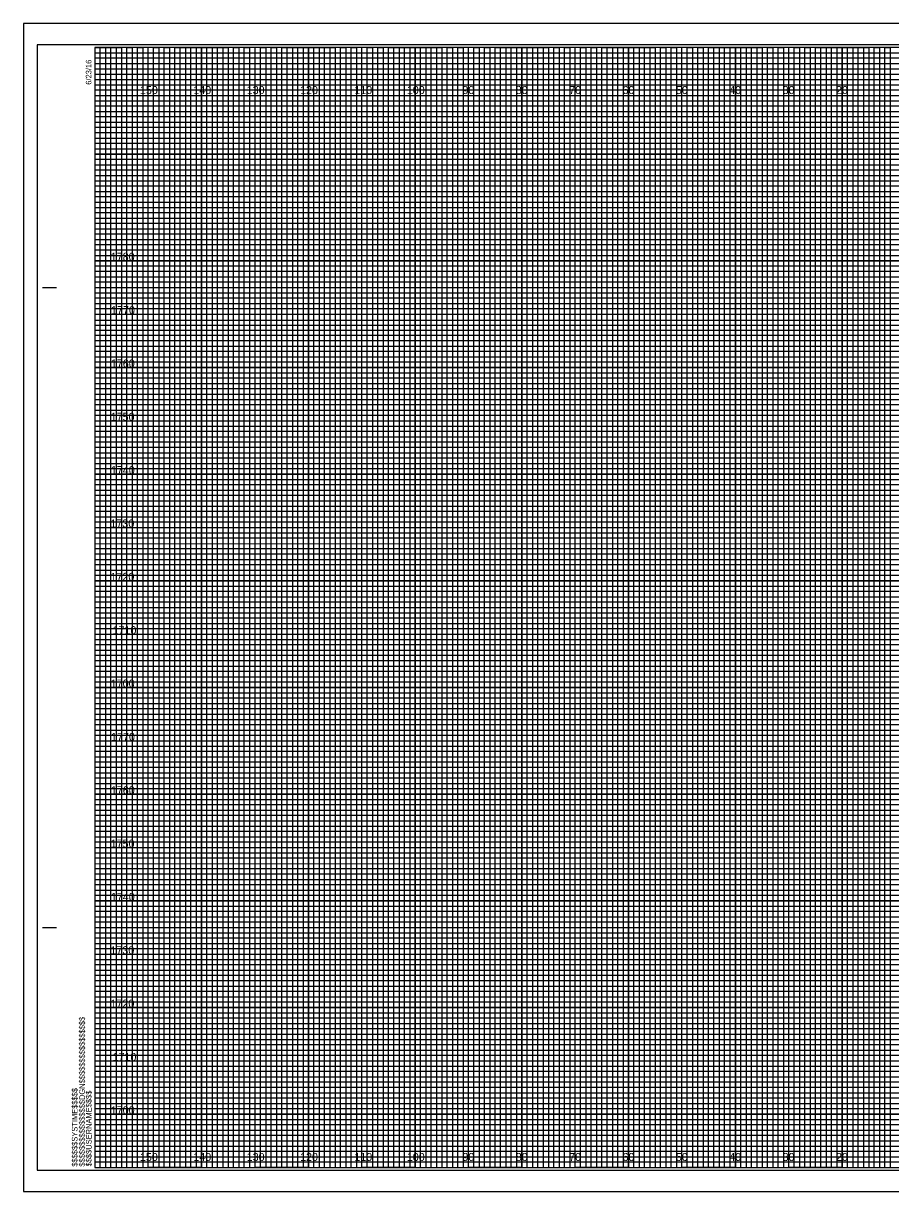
# Model space of a CAD drawing. Extents: x -419 to 4739, y -630 to 13534.
# Drawn here: x 4400.7 to 4563.2, y 665 to 884 of the extents above; entities that cross this region are included whole.
import ezdxf

# ---------------------------------------------------------------- set-up
doc = ezdxf.new("R2010")
doc.units = 0
for name, color, linetype in [('Old_Level_62', 7, 'Continuous'), ('Pattern 1', 7, 'Continuous'), ('Pattern 18', 7, 'Continuous'), ('Pattern 4', 7, 'Continuous'), ('Pattern 5', 7, 'Continuous'), ('Prop Dimension', 7, 'Continuous'), ('Prop Horizontal Alignment', 7, 'Continuous'), ('Raster_Level_0', 7, 'Continuous'), ('Scratch_Level_0', 7, 'Continuous'), ('Scratch_Level_3', 7, 'Continuous'), ('Scratch_Level_5', 7, 'Continuous')]:
    doc.layers.add(name, color=color, linetype=linetype)

msp = doc.modelspace()

# ---------------------------------------------------------------- linework, layer by layer
at = {"layer": 'Old_Level_62'}
for p, q in [((4404.33, 834.53), (4406.83, 834.53)), ((4404.43, 834.53), (4406.93, 834.53)), ((4404.33, 714.53), (4406.83, 714.53)), ((4404.43, 714.53), (4406.93, 714.53)), ((4414.13, 669.53), (4414.13, 669.53)), ((4414.13, 669.53), (4414.13, 669.53)), ((4414.13, 669.53), (4414.13, 669.53)), ((4414.13, 669.53), (4414.13, 669.53)), ((4414.13, 669.53), (4414.13, 669.53)), ((4414.13, 669.53), (4414.13, 669.53)), ((4414.13, 669.53), (4414.13, 669.53))]:
    msp.add_line(p, q, dxfattribs=at)
msp.add_lwpolyline([(4734.13, 879.53), (4414.13, 879.53), (4414.13, 669.53), (4734.13, 669.53)], close=True, dxfattribs=at)
at = {"layer": 'Pattern 18'}
msp.add_lwpolyline([(4400.73, 665.03), (4737.43, 665.03), (4737.43, 884.03), (4400.73, 884.03)], close=True, dxfattribs=at)
at = {"layer": 'Pattern 4'}
for p, q in [((4414.13, 878.53), (4674.13, 878.53)), ((4674.13, 877.51), (4414.13, 877.51)), ((4414.13, 877.51), (4414.13, 876.53)), ((4414.13, 876.53), (4674.13, 876.53)), ((4674.13, 875.42), (4414.13, 875.42)), ((4414.13, 875.42), (4414.13, 873.53)), ((4414.13, 873.53), (4734.13, 873.53))]:
    msp.add_line(p, q, dxfattribs=at)
for points in [[(4414.13, 872.53), (4684.13, 872.53), (4734.13, 872.53), (4734.13, 871.53), (4414.13, 871.53)], [(4414.13, 870.53), (4734.13, 870.53), (4734.13, 868.53), (4414.13, 868.53)], [(4414.13, 867.53), (4734.13, 867.53), (4734.13, 866.53), (4414.13, 866.51)], [(4414.13, 865.53), (4734.13, 865.53), (4734.13, 863.53), (4414.13, 863.53)], [(4414.13, 862.53), (4734.13, 862.53), (4734.13, 861.53), (4414.13, 861.53)], [(4414.13, 860.53), (4734.13, 860.53), (4734.13, 858.53), (4414.13, 858.53)], [(4414.13, 857.53), (4734.13, 857.53), (4734.13, 856.53), (4414.13, 856.53)], [(4414.13, 855.53), (4734.13, 855.53), (4734.13, 853.53), (4414.13, 853.53)], [(4414.13, 852.53), (4734.13, 852.53), (4734.13, 851.53), (4414.13, 851.53)], [(4414.13, 850.53), (4734.13, 850.53), (4734.13, 848.53), (4414.13, 848.53)], [(4414.13, 847.53), (4734.13, 847.53), (4734.13, 846.53), (4414.13, 846.53)], [(4414.13, 845.53), (4734.13, 845.53), (4734.13, 843.48), (4734.13, 842.53), (4734.13, 841.53), (4414.13, 841.53)], [(4414.13, 843.53), (4734.13, 843.53), (4734.13, 842.53), (4414.13, 842.53)], [(4414.13, 840.53), (4734.13, 840.53), (4734.13, 838.53), (4414.13, 838.56)], [(4414.13, 838.56), (4734.13, 838.53), (4734.13, 837.53), (4414.13, 837.53)], [(4414.13, 836.53), (4734.13, 836.53), (4734.13, 835.53), (4414.13, 835.53)], [(4414.13, 833.53), (4734.13, 833.53), (4734.13, 832.53), (4414.13, 832.53)], [(4414.13, 831.53), (4734.13, 831.53), (4734.13, 830.53), (4414.13, 830.53)], [(4414.06, 828.42), (4734.13, 828.42), (4734.13, 827.41), (4414.06, 827.41)], [(4414.13, 826.53), (4734.13, 826.53), (4734.13, 825.53), (4414.13, 825.53)], [(4414.13, 823.53), (4734.13, 823.53), (4734.13, 822.53), (4414.13, 822.53)], [(4414.13, 821.53), (4734.13, 821.53), (4734.13, 820.53), (4414.13, 820.53)], [(4414.13, 818.53), (4734.13, 818.53), (4734.13, 817.53), (4414.13, 817.53)], [(4414.13, 816.53), (4734.13, 816.53), (4734.13, 815.53), (4414.13, 815.53)], [(4414.13, 813.53), (4734.13, 813.53), (4734.13, 812.53), (4414.13, 812.53)], [(4414.13, 811.53), (4734.13, 811.53), (4734.13, 810.53), (4414.13, 810.53)], [(4414.13, 808.53), (4734.13, 808.53), (4734.12, 807.51), (4414.13, 807.53)], [(4414.13, 806.53), (4734.13, 806.53), (4734.13, 805.53), (4414.13, 805.53)], [(4414.13, 803.53), (4734.13, 803.53), (4734.13, 802.53), (4414.13, 802.53)], [(4414.13, 801.53), (4734.13, 801.53), (4734.13, 800.53), (4414.13, 800.53)], [(4414.13, 798.53), (4734.13, 798.53), (4734.13, 797.53), (4414.13, 797.53)], [(4414.13, 796.53), (4734.13, 796.53), (4734.13, 795.53), (4414.13, 795.53)], [(4414.13, 793.53), (4734.13, 793.53), (4734.13, 792.53), (4414.13, 792.53)], [(4414.13, 791.53), (4734.13, 791.53), (4734.13, 790.53), (4414.13, 790.53)], [(4414.13, 788.53), (4734.13, 788.53), (4734.13, 787.53), (4414.13, 787.53)], [(4414.13, 786.52), (4734.2, 786.44), (4734.13, 785.53), (4414.13, 785.53)], [(4414.13, 783.53), (4734.13, 783.53), (4734.13, 782.53), (4414.13, 782.53)], [(4414.13, 781.53), (4734.13, 781.53), (4734.13, 780.53), (4414.13, 780.53)], [(4414.13, 778.53), (4734.13, 778.53), (4734.13, 777.53), (4414.13, 777.53)], [(4414.13, 776.53), (4734.13, 776.53), (4734.13, 775.53), (4414.13, 775.53)], [(4414.13, 773.53), (4734.13, 773.53), (4734.13, 772.53), (4414.13, 772.53)], [(4414.13, 771.53), (4734.13, 771.53), (4734.13, 770.53), (4414.13, 770.53)], [(4414.13, 768.53), (4734.13, 768.53), (4734.13, 767.53), (4414.13, 767.53)], [(4414.13, 766.53), (4734.13, 766.53), (4734.13, 765.53), (4414.13, 765.53)], [(4414.13, 763.53), (4734.13, 763.53), (4734.13, 762.53), (4414.13, 762.53)], [(4414.13, 761.53), (4734.13, 761.53), (4734.13, 760.53), (4414.13, 760.53)], [(4414.13, 758.53), (4734.13, 758.53), (4734.13, 757.53), (4414.13, 757.53)], [(4414.13, 756.53), (4734.13, 756.53), (4734.13, 755.53), (4414.13, 755.53)], [(4414.13, 753.53), (4734.13, 753.53), (4734.13, 752.53), (4414.13, 752.53)], [(4414.13, 751.53), (4734.13, 751.53), (4734.13, 750.53), (4414.13, 750.53)], [(4414.13, 748.53), (4734.13, 748.53), (4734.12, 747.51), (4414.13, 747.53)], [(4414.13, 746.53), (4734.13, 746.53), (4734.13, 745.53), (4414.13, 745.53)], [(4414.13, 743.53), (4734.13, 743.53), (4734.13, 742.53), (4414.13, 742.53)], [(4414.13, 741.53), (4734.13, 741.53), (4734.13, 740.53), (4414.13, 740.53)], [(4414.13, 738.53), (4734.13, 738.53), (4734.13, 737.53), (4414.13, 737.53)], [(4414.13, 736.53), (4734.13, 736.53), (4734.13, 735.53), (4414.13, 735.53)], [(4414.13, 733.53), (4734.13, 733.53), (4734.13, 732.53), (4414.13, 732.53)], [(4414.13, 731.53), (4734.13, 731.53), (4734.13, 730.53), (4414.13, 730.53)], [(4414.13, 728.53), (4734.13, 728.53), (4734.13, 727.53), (4414.13, 727.53)], [(4414.13, 726.52), (4734.2, 726.44), (4734.13, 725.53), (4414.13, 725.53)], [(4414.13, 723.53), (4734.13, 723.53), (4734.13, 722.53), (4414.13, 722.53)], [(4414.13, 721.53), (4734.13, 721.53), (4734.13, 720.53), (4414.13, 720.53)], [(4414.13, 718.53), (4734.13, 718.53), (4734.13, 717.53), (4414.13, 717.53)], [(4414.13, 716.53), (4734.13, 716.53), (4734.13, 715.53), (4414.13, 715.53)], [(4414.13, 713.53), (4734.13, 713.53), (4734.13, 712.53), (4414.13, 712.53)], [(4414.13, 711.53), (4734.13, 711.53), (4734.13, 710.53), (4414.13, 710.53)], [(4414.13, 708.53), (4734.13, 708.53), (4734.13, 707.53), (4414.13, 707.53)], [(4414.13, 706.53), (4734.13, 706.53), (4734.13, 705.53), (4414.13, 705.53)], [(4414.13, 703.53), (4734.13, 703.53), (4734.13, 702.53), (4414.13, 702.53)], [(4414.13, 701.53), (4734.13, 701.53), (4734.13, 700.53), (4414.13, 700.53)], [(4414.13, 698.53), (4734.13, 698.53), (4734.13, 697.53), (4414.13, 697.53)], [(4414.13, 696.53), (4734.13, 696.53), (4734.13, 695.53), (4414.13, 695.53)], [(4414.13, 693.53), (4734.13, 693.53), (4734.13, 692.53), (4414.13, 692.53)], [(4414.13, 691.53), (4734.13, 691.53), (4734.13, 690.53), (4414.13, 690.53)], [(4414.13, 688.53), (4734.13, 688.53), (4734.13, 687.53), (4414.13, 687.53)], [(4414.13, 686.53), (4734.13, 686.53), (4734.13, 685.53), (4414.13, 685.53)], [(4414.13, 683.53), (4734.13, 683.53), (4734.13, 682.53), (4414.13, 682.53)], [(4414.13, 681.53), (4734.13, 681.53), (4734.13, 680.53), (4414.13, 680.53)], [(4414.13, 678.53), (4734.13, 678.53), (4734.13, 677.53), (4414.13, 677.53)], [(4414.13, 676.53), (4734.13, 676.53), (4734.13, 675.53), (4414.13, 675.53)], [(4414.13, 673.53), (4734.13, 673.53), (4734.13, 672.53), (4414.13, 672.53)], [(4414.13, 671.53), (4734.13, 671.53), (4734.13, 670.53), (4414.13, 670.53)]]:
    msp.add_lwpolyline(points, dxfattribs=at)
at = {"layer": 'Pattern 5'}
for p, q in [((4737.43, 884.03), (4400.73, 884.03)), ((4400.73, 884.03), (4400.73, 665.03)), ((4400.73, 665.03), (4737.43, 665.03))]:
    msp.add_line(p, q, dxfattribs=at)
at = {"layer": 'Prop Dimension'}
for points in [[(4414.13, 669.53), (4415.13, 669.53), (4415.13, 879.53), (4416.13, 879.53), (4416.13, 669.53)], [(4416.13, 669.53), (4417.13, 669.53), (4417.13, 879.53), (4418.13, 879.53), (4418.13, 669.53)], [(4419.13, 669.53), (4420.13, 669.53), (4420.13, 879.53), (4421.13, 879.53), (4421.13, 669.53)], [(4421.13, 669.53), (4422.13, 669.53), (4422.13, 879.53), (4423.13, 879.53), (4423.13, 669.53)], [(4424.13, 669.53), (4425.13, 669.53), (4425.13, 879.53), (4426.13, 879.53), (4426.13, 669.53)], [(4426.13, 669.53), (4427.13, 669.53), (4427.13, 879.53), (4428.13, 879.53), (4428.13, 669.53)], [(4429.13, 669.53), (4430.13, 669.53), (4430.13, 879.53), (4431.13, 879.53), (4431.13, 669.53)], [(4431.13, 669.53), (4432.13, 669.53), (4432.13, 879.53), (4433.13, 879.53), (4433.13, 669.53)], [(4434.13, 669.53), (4435.13, 669.53), (4435.13, 879.53), (4436.13, 879.53), (4436.13, 669.53)], [(4436.13, 669.53), (4437.13, 669.53), (4437.13, 879.53), (4438.13, 879.53), (4438.13, 669.53)], [(4439.13, 669.53), (4440.13, 669.53), (4440.13, 879.53), (4441.13, 879.53), (4441.13, 669.53)], [(4441.13, 669.53), (4442.13, 669.53), (4442.13, 879.53), (4443.13, 879.53), (4443.13, 669.53)], [(4444.13, 669.53), (4445.13, 669.53), (4445.13, 879.53), (4446.13, 879.53), (4446.13, 669.53)], [(4446.13, 669.53), (4447.13, 669.53), (4447.13, 879.53), (4448.13, 879.53), (4448.13, 669.53)], [(4449.13, 669.53), (4450.13, 669.53), (4450.13, 879.53), (4451.13, 879.53), (4451.13, 669.53)], [(4451.13, 669.53), (4452.13, 669.53), (4452.13, 879.53), (4453.13, 879.53), (4453.13, 669.53)], [(4454.13, 669.53), (4455.13, 669.53), (4455.13, 879.53), (4456.13, 879.53), (4456.13, 669.53)], [(4456.13, 669.53), (4457.13, 669.53), (4457.13, 879.53), (4458.13, 879.53), (4458.13, 669.53)], [(4459.13, 669.53), (4460.13, 669.53), (4460.13, 879.53), (4461.13, 879.53), (4461.13, 669.53)], [(4461.13, 669.53), (4462.13, 669.53), (4462.13, 879.53), (4463.13, 879.53), (4463.13, 669.53)], [(4464.13, 669.53), (4465.13, 669.53), (4465.13, 879.53), (4466.13, 879.53), (4466.13, 669.53)], [(4466.13, 669.53), (4467.13, 669.53), (4467.13, 879.53), (4468.13, 879.53), (4468.13, 669.53)], [(4469.13, 669.53), (4470.13, 669.53), (4470.13, 879.53), (4471.13, 879.53), (4471.13, 669.53)], [(4471.13, 669.53), (4472.13, 669.53), (4472.13, 879.53), (4473.13, 879.53), (4473.13, 669.53)], [(4474.13, 669.53), (4475.13, 669.53), (4475.13, 879.53), (4476.13, 879.53), (4476.13, 669.53)], [(4476.13, 669.53), (4477.13, 669.53), (4477.13, 879.53), (4478.13, 879.53), (4478.13, 669.53)], [(4479.13, 669.53), (4480.13, 669.53), (4480.13, 879.53), (4481.13, 879.53), (4481.13, 669.53)], [(4481.13, 669.53), (4482.13, 669.53), (4482.13, 879.53), (4483.13, 879.53), (4483.13, 669.53)], [(4484.13, 669.53), (4485.13, 669.53), (4485.13, 879.53), (4486.13, 879.53), (4486.13, 669.53)], [(4486.13, 669.53), (4487.13, 669.53), (4487.13, 879.53), (4488.13, 879.53), (4488.13, 669.53)], [(4489.13, 669.53), (4490.13, 669.53), (4490.13, 879.53), (4491.13, 879.53), (4491.13, 669.53)], [(4491.13, 669.53), (4492.13, 669.53), (4492.13, 879.53), (4493.13, 879.53), (4493.13, 669.53)], [(4494.13, 669.53), (4495.13, 669.53), (4495.13, 879.53), (4496.13, 879.53), (4496.13, 669.53)], [(4496.13, 669.53), (4497.13, 669.53), (4497.13, 879.53), (4498.13, 879.53), (4498.13, 669.53)], [(4499.13, 669.53), (4500.13, 669.53), (4500.13, 879.53), (4501.13, 879.53), (4501.13, 669.53)], [(4501.13, 669.53), (4502.13, 669.53), (4502.13, 879.53), (4503.13, 879.53), (4503.13, 669.53)], [(4504.13, 669.53), (4505.13, 669.53), (4505.13, 879.53), (4506.13, 879.53), (4506.13, 669.53)], [(4506.13, 669.53), (4507.13, 669.53), (4507.13, 879.53), (4508.13, 879.53), (4508.13, 669.53)], [(4509.13, 669.53), (4510.13, 669.53), (4510.13, 879.53), (4511.13, 879.53), (4511.13, 669.53)], [(4511.13, 669.53), (4512.13, 669.53), (4512.13, 879.53), (4513.13, 879.53), (4513.13, 669.53)], [(4514.13, 669.53), (4515.13, 669.53), (4515.13, 879.53), (4516.13, 879.53), (4516.13, 669.53)], [(4516.13, 669.53), (4517.13, 669.53), (4517.13, 879.53), (4518.13, 879.53), (4518.13, 669.53)], [(4519.13, 669.53), (4520.13, 669.53), (4520.13, 879.53), (4521.13, 879.53), (4521.13, 669.53)], [(4521.13, 669.53), (4522.13, 669.53), (4522.13, 879.53), (4523.13, 879.53), (4523.13, 669.53)], [(4524.13, 669.53), (4525.13, 669.53), (4525.13, 879.53), (4526.13, 879.53), (4526.13, 669.53)], [(4526.13, 669.53), (4527.13, 669.53), (4527.13, 879.53), (4528.13, 879.53), (4528.13, 669.53)], [(4529.13, 669.53), (4530.13, 669.53), (4530.13, 879.53), (4531.13, 879.53), (4531.13, 669.53)], [(4531.13, 669.53), (4532.13, 669.53), (4532.13, 879.53), (4533.13, 879.53), (4533.13, 669.53)], [(4534.13, 669.53), (4535.13, 669.53), (4535.13, 879.53), (4536.13, 879.53), (4536.13, 669.53)], [(4536.13, 669.53), (4537.13, 669.53), (4537.13, 879.53), (4538.13, 879.53), (4538.13, 669.53)], [(4539.13, 669.53), (4540.13, 669.53), (4540.13, 879.53), (4541.13, 879.53), (4541.13, 669.53)], [(4541.13, 669.53), (4542.13, 669.53), (4542.13, 879.53), (4543.13, 879.53), (4543.13, 669.53)], [(4544.13, 669.53), (4545.13, 669.53), (4545.13, 879.53), (4546.13, 879.53), (4546.13, 669.53)], [(4546.13, 669.53), (4547.13, 669.53), (4547.13, 879.53), (4548.13, 879.53), (4548.13, 669.53)], [(4549.13, 669.53), (4550.13, 669.53), (4550.13, 879.53), (4551.13, 879.53), (4551.13, 669.53)], [(4551.13, 669.53), (4552.13, 669.53), (4552.13, 879.53), (4553.13, 879.53), (4553.13, 669.53)], [(4554.13, 669.53), (4555.13, 669.53), (4555.13, 879.53), (4556.13, 879.53), (4556.13, 669.53)], [(4556.13, 669.53), (4557.13, 669.53), (4557.13, 879.53), (4558.13, 879.53), (4558.13, 669.53)], [(4559.13, 669.53), (4560.13, 669.53), (4560.13, 879.53), (4561.13, 879.53), (4561.13, 669.53)], [(4561.13, 669.53), (4562.13, 669.53), (4562.13, 879.53), (4563.13, 879.53), (4563.13, 669.53)]]:
    msp.add_lwpolyline(points, dxfattribs=at)
at = {"layer": 'Prop Horizontal Alignment'}
for points in [[(4414.13, 879.53), (4419.13, 879.53), (4419.13, 669.53), (4429.13, 669.53), (4429.13, 879.53), (4439.13, 879.53), (4439.13, 669.53), (4449.13, 669.53), (4449.13, 879.53), (4459.13, 879.53), (4459.13, 669.53), (4469.13, 669.53), (4469.13, 879.53), (4479.13, 879.53), (4479.13, 669.53), (4489.13, 669.53), (4489.13, 879.53), (4499.13, 879.53), (4499.13, 669.53), (4509.13, 669.53), (4509.13, 879.53), (4519.13, 879.53), (4519.13, 669.53), (4529.13, 669.53), (4529.13, 879.53), (4539.13, 879.53), (4539.13, 669.53), (4549.13, 669.53), (4549.13, 879.53), (4559.13, 879.53), (4559.13, 669.53), (4569.13, 669.53)], [(4414.13, 874.53), (4689.13, 874.53)], [(4414.13, 854.53), (4734.13, 854.53), (4734.13, 864.53), (4414.13, 864.53)], [(4414.13, 834.53), (4734.13, 834.53), (4734.13, 844.53), (4414.13, 844.53)], [(4414.13, 814.53), (4734.13, 814.53), (4734.13, 824.53), (4414.13, 824.53)], [(4414.13, 794.53), (4734.13, 794.53), (4734.13, 804.53), (4414.13, 804.53)], [(4414.13, 774.53), (4734.13, 774.53), (4734.13, 784.53), (4414.13, 784.53)], [(4414.13, 754.53), (4734.13, 754.53), (4734.13, 764.53), (4414.13, 764.53)], [(4414.13, 734.53), (4734.13, 734.53), (4734.13, 744.53), (4414.13, 744.53)], [(4414.13, 714.53), (4734.13, 714.53), (4734.13, 724.53), (4414.13, 724.53)], [(4414.13, 694.53), (4734.13, 694.53), (4734.13, 704.53), (4414.13, 704.53)], [(4414.13, 674.53), (4734.13, 674.53), (4734.13, 684.53), (4414.13, 684.53)]]:
    msp.add_lwpolyline(points, dxfattribs=at)
at = {"layer": 'Scratch_Level_0'}
for p, q in [((4424.13, 669.53), (4424.13, 879.53)), ((4434.13, 669.53), (4434.13, 879.53)), ((4444.13, 669.53), (4444.13, 879.53)), ((4454.13, 669.53), (4454.13, 879.53)), ((4464.13, 669.53), (4464.13, 879.53)), ((4474.13, 669.53), (4474.13, 879.53)), ((4484.13, 669.53), (4484.13, 879.53)), ((4494.13, 669.53), (4494.13, 879.53)), ((4504.13, 669.53), (4504.13, 879.53)), ((4514.13, 669.53), (4514.13, 879.53)), ((4524.13, 669.53), (4524.13, 879.53)), ((4534.13, 669.53), (4534.13, 879.53)), ((4544.13, 669.53), (4544.13, 879.53)), ((4554.13, 669.53), (4554.13, 879.53)), ((4414.13, 869.53), (4734.13, 869.53)), ((4414.13, 859.53), (4734.13, 859.53)), ((4414.13, 849.53), (4734.13, 849.53)), ((4414.13, 839.53), (4734.13, 839.53)), ((4414.13, 829.53), (4734.13, 829.53)), ((4414.13, 819.53), (4734.13, 819.53)), ((4414.13, 809.53), (4734.13, 809.53)), ((4414.13, 799.53), (4734.13, 799.53)), ((4414.13, 789.53), (4734.13, 789.53)), ((4414.13, 779.53), (4734.13, 779.53)), ((4414.13, 769.53), (4734.13, 769.53)), ((4414.13, 759.53), (4734.13, 759.53)), ((4414.13, 749.53), (4734.13, 749.53)), ((4414.13, 739.53), (4734.13, 739.53)), ((4414.13, 729.53), (4734.13, 729.53)), ((4414.13, 719.53), (4734.13, 719.53)), ((4414.13, 709.53), (4734.13, 709.53)), ((4414.13, 699.53), (4734.13, 699.53)), ((4414.13, 689.53), (4734.13, 689.53)), ((4414.13, 679.53), (4734.13, 679.53))]:
    msp.add_line(p, q, dxfattribs=at)
at = {"layer": 'Scratch_Level_3'}
for p, q in [((4424.13, 879.53), (4414.13, 879.53)), ((4424.13, 669.53), (4424.13, 879.53)), ((4444.13, 879.53), (4434.13, 879.53)), ((4434.13, 879.53), (4434.13, 669.53)), ((4444.13, 669.53), (4444.13, 879.53)), ((4464.13, 879.53), (4454.13, 879.53)), ((4454.13, 879.53), (4454.13, 669.53)), ((4464.13, 669.53), (4464.13, 879.53)), ((4484.13, 879.53), (4474.13, 879.53)), ((4474.13, 879.53), (4474.13, 669.53)), ((4484.13, 669.53), (4484.13, 879.53)), ((4504.13, 879.53), (4494.13, 879.53)), ((4494.13, 879.53), (4494.13, 669.53)), ((4504.13, 669.53), (4504.13, 879.53)), ((4524.13, 879.53), (4514.13, 879.53)), ((4514.13, 879.53), (4514.13, 669.53)), ((4524.13, 669.53), (4524.13, 879.53)), ((4544.13, 879.53), (4534.13, 879.53)), ((4534.13, 879.53), (4534.13, 669.53)), ((4544.13, 669.53), (4544.13, 879.53)), ((4564.13, 879.53), (4554.13, 879.53)), ((4554.13, 879.53), (4554.13, 669.53)), ((4434.13, 669.53), (4424.13, 669.53)), ((4454.13, 669.53), (4444.13, 669.53)), ((4474.13, 669.53), (4464.13, 669.53)), ((4494.13, 669.53), (4484.13, 669.53)), ((4514.13, 669.53), (4504.13, 669.53)), ((4534.13, 669.53), (4524.13, 669.53)), ((4554.13, 669.53), (4544.13, 669.53))]:
    msp.add_line(p, q, dxfattribs=at)
for points in [[(4414.13, 869.53), (4734.13, 869.53), (4734.13, 859.53), (4414.13, 859.53)], [(4414.13, 849.53), (4734.13, 849.53), (4734.13, 839.53), (4414.13, 839.53)], [(4414.13, 829.53), (4734.13, 829.53), (4734.13, 819.53), (4414.13, 819.53)], [(4414.13, 809.53), (4734.13, 809.53), (4734.13, 799.53), (4414.13, 799.53)], [(4414.13, 789.53), (4734.13, 789.53), (4734.13, 779.53), (4414.13, 779.53)], [(4414.13, 769.53), (4734.13, 769.53), (4734.13, 759.53), (4414.13, 759.53)], [(4414.13, 749.53), (4734.13, 749.53), (4734.13, 739.53), (4414.13, 739.53)], [(4414.13, 729.53), (4734.13, 729.53), (4734.13, 719.53), (4414.13, 719.53)], [(4414.13, 709.53), (4734.13, 709.53), (4734.13, 699.53), (4414.13, 699.53)], [(4414.13, 689.53), (4734.13, 689.53), (4734.13, 679.53), (4414.13, 679.53)]]:
    msp.add_lwpolyline(points, dxfattribs=at)
at = {"layer": 'Scratch_Level_5'}
msp.add_lwpolyline([(4403.33, 669.03), (4736.53, 669.03), (4736.53, 880.03), (4403.33, 880.03)], close=True, dxfattribs=at)

# ---------------------------------------------------------------- texts
at = {"layer": 'Old_Level_62'}
for s, p in [('6/23/16', (4413.48, 872.53)), ('$$$$$$$$$$$$$$$$DGN$$$$$$$$$$$$$$$$', (4412.25, 669.71)), ('$$$$$$SYSTIME$$$$$', (4410.87, 669.71)), ('$$$$USERNAME$$$$', (4413.51, 669.76))]:
    msp.add_text(s, height=1.05, rotation=90, dxfattribs=at).set_placement(p)
at = {"layer": 'Pattern 1'}
for s, p in [('1780', (4417.11, 839.53)), ('1770', (4417.17, 829.53)), ('1760', (4417.13, 819.53)), ('1750', (4417.09, 809.53)), ('1740', (4417.13, 799.53)), ('1730', (4417.05, 789.53)), ('1720', (4417.06, 779.53)), ('1710', (4417.44, 769.53)), ('1700', (4417.11, 759.53)), ('1770', (4417.17, 749.53)), ('1760', (4417.13, 739.53)), ('1750', (4417.09, 729.53)), ('1740', (4417.13, 719.53)), ('1730', (4417.05, 709.53)), ('1720', (4417.06, 699.53)), ('1710', (4417.44, 689.53)), ('1700', (4417.11, 679.53))]:
    msp.add_text(s, height=1.5, dxfattribs=at).set_placement(p)
at = {"layer": 'Raster_Level_0'}
for s, p in [('150', (4422.58, 870.78)), ('140', (4432.58, 870.78)), ('130', (4442.58, 870.78)), ('120', (4452.58, 870.78)), ('110', (4462.75, 870.78)), ('100', (4472.58, 870.78)), ('90', (4482.99, 870.78)), ('80', (4492.99, 870.78)), ('70', (4502.99, 870.78)), ('60', (4512.99, 870.78)), ('50', (4522.99, 870.78)), ('40', (4532.99, 870.78)), ('30', (4542.99, 870.78)), ('20', (4552.99, 870.78)), ('150', (4422.58, 670.78)), ('140', (4432.58, 670.78)), ('130', (4442.58, 670.78)), ('120', (4452.58, 670.78)), ('110', (4462.75, 670.78)), ('100', (4472.58, 670.78)), ('90', (4482.99, 670.78)), ('80', (4492.99, 670.78)), ('70', (4502.99, 670.78)), ('60', (4512.99, 670.78)), ('50', (4522.99, 670.78)), ('40', (4532.99, 670.78)), ('30', (4542.99, 670.78)), ('20', (4552.99, 670.78))]:
    msp.add_text(s, height=1.5, dxfattribs=at).set_placement(p)

doc.saveas('drawing.dxf')
